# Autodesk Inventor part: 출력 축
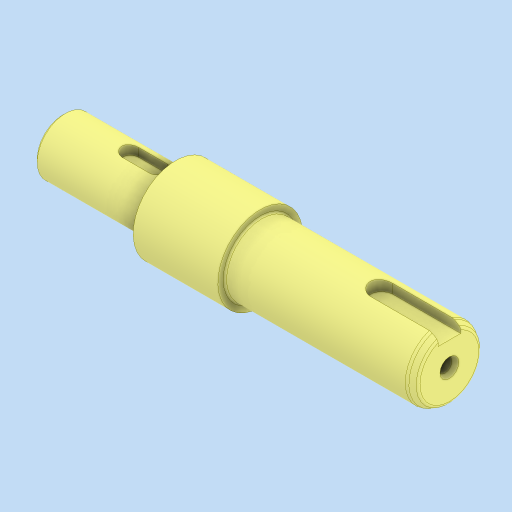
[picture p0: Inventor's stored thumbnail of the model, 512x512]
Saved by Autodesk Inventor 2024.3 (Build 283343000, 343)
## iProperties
Created: 2025-11
Part Number: 출력 축
Material: 강철, 탄소
Document SubType Name: Modeling
Designer: PC2-03
Density: 7.85 g/cm^3
Appearance: 기본값
Author: jhkim
Sending System: Autodesk Inventor 2026
Preprocessor: ST-DEVELOPER v20.1
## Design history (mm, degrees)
feature "솔리드1"
node "솔리드2"
